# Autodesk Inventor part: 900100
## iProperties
Created: 2007-12
Part Number: 900100
Document SubType Name: Modeling
Designer: EP
Density: 1.425 g/cm^3
Mass: 54.0389 g
Surface Area: 125.096 cm^2
Volume: 37.922 cm^3
Material: Acetal Resin, Black
Description: 1200 POWER SEAT SWITCH CONTROL
Component Category: Electrical
Author: EP
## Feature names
1. Extrusion1
2. Extrusion2
3. Chamfer1
4. Extrusion3
5. Extrusion4
6. Fillet1
7. Rectangular Pattern1
8. Extrusion5
9. Fillet2
10. Fillet3
11. Extrusion6
12. Fillet4
13. Fillet5
14. Extrusion7
15. Extrusion8
16. Fillet6
17. Fillet7
18. Fillet8
19. Mirror1
20. Extrusion9
21. Extrusion10
22. Mirror2
23. Fillet9
24. Fillet10
25. Fillet11
26. Extrusion11
27. Extrusion12
28. Fillet13
29. Mirror3
